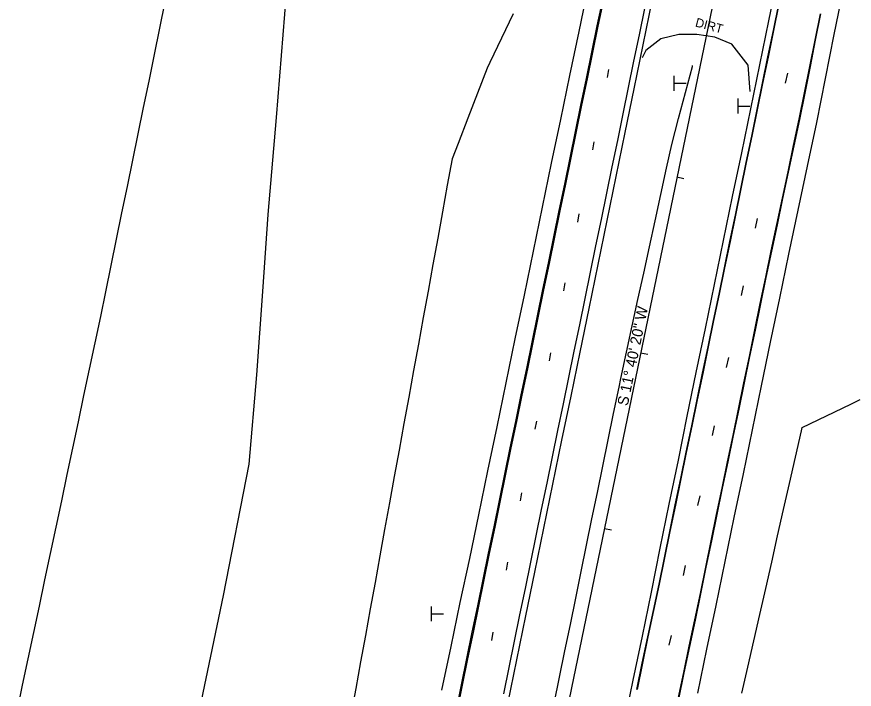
# Model space of a CAD drawing. Extents: x 2132221 to 2141942, y 535736 to 547298.
# Drawn here: x 2135703.9 to 2136170.8, y 536120.5 to 536495.3 of the extents above; entities that cross this region are included whole.
import ezdxf

# ---------------------------------------------------------------- set-up
doc = ezdxf.new("R2010")
doc.units = 0
for name, color, linetype in [('RD_EX_BldgApp', 7, 'Continuous'), ('RD_EX_Conc', 7, 'Continuous'), ('RD_EX_Driveway', 7, 'Continuous'), ('RD_EX_Driveway_txCode', 7, 'Continuous'), ('RD_EX_Fence_Other', 7, 'Continuous'), ('RD_EX_GuardRail', 7, 'Continuous'), ('RD_EX_Misc', 7, 'Continuous'), ('RD_EX_Road', 7, 'Continuous'), ('RD_EX_VEG', 7, 'Continuous'), ('RD_HC_Cl', 7, 'Continuous'), ('RD_HC_Data', 7, 'Continuous'), ('RD_HC_Data_Tic', 7, 'Continuous'), ('TOPO_E_TLIML-Line', 7, 'Continuous')]:
    doc.layers.add(name, color=color, linetype=linetype)

msp = doc.modelspace()

# ---------------------------------------------------------------- linework, layer by layer
at = {"layer": 'RD_EX_BldgApp'}
for p, q in [((2136070.24, 536462.33), (2136070.24, 536458.22)), ((2136070.24, 536458.22), (2136070.24, 536454.1)), ((2136070.24, 536458.22), (2136077.1, 536458.22)), ((2136105.85, 536449.67), (2136105.85, 536445.56)), ((2136105.85, 536445.56), (2136105.85, 536441.44)), ((2136105.85, 536445.56), (2136112.7, 536445.56)), ((2135934.97, 536166.67), (2135934.97, 536162.55)), ((2135934.97, 536162.55), (2135934.97, 536158.44)), ((2135934.97, 536162.55), (2135941.83, 536162.55))]:
    msp.add_line(p, q, dxfattribs=at)
at = {"layer": 'RD_EX_Conc'}
for points in [[(2135948.82, 536108.22), (2135951.86, 536122.91), (2135954.89, 536137.6), (2135957.9, 536152.29), (2135960.89, 536166.99), (2135963.94, 536181.68), (2135966.99, 536196.37), (2135970.01, 536211.06), (2135973.01, 536225.75), (2135976, 536240.45), (2135979.05, 536255.14), (2135982.1, 536269.83), (2135985.16, 536284.51), (2135988.2, 536299.2), (2135991.22, 536313.89), (2135994.25, 536328.58), (2135997.27, 536343.28), (2136000.3, 536357.97), (2136003.32, 536372.66), (2136006.35, 536387.35), (2136009.4, 536402.04), (2136012.43, 536416.73), (2136015.45, 536431.42), (2136018.46, 536446.11), (2136021.47, 536460.81), (2136024.49, 536475.5), (2136027.54, 536490.19), (2136030.62, 536504.87)], [(2136049.66, 536120.4), (2136052.66, 536135.1), (2136055.66, 536149.8), (2136058.9, 536164.45), (2136062.05, 536179.11), (2136065.03, 536193.81), (2136068.02, 536208.51), (2136071.02, 536223.21), (2136074.08, 536237.89), (2136077.14, 536252.58), (2136080.19, 536267.26), (2136083.25, 536281.95), (2136086.31, 536296.63), (2136089.35, 536311.32), (2136092.39, 536326.01), (2136095.42, 536340.7), (2136098.46, 536355.39), (2136101.49, 536370.08), (2136104.53, 536384.77), (2136107.56, 536399.46), (2136110.6, 536414.15), (2136113.63, 536428.84), (2136116.66, 536443.53), (2136119.69, 536458.22), (2136122.72, 536472.91), (2136125.75, 536487.6), (2136128.79, 536502.29)], [(2136073.01, 536115.07), (2136076.05, 536129.75), (2136079.09, 536144.44), (2136082.25, 536159.11), (2136085.36, 536173.78), (2136088.34, 536188.48), (2136091.33, 536203.18), (2136094.33, 536217.88), (2136097.43, 536232.55), (2136100.51, 536247.23), (2136103.55, 536261.92), (2136106.6, 536276.61), (2136109.66, 536291.29), (2136112.7, 536305.98), (2136115.73, 536320.67), (2136118.76, 536335.36), (2136121.8, 536350.05), (2136124.84, 536364.74), (2136127.94, 536379.42), (2136131.06, 536394.09), (2136134.21, 536408.75), (2136137.32, 536423.43), (2136140.4, 536438.11), (2136143.44, 536452.8), (2136146.42, 536467.5), (2136149.28, 536482.23), (2136152.25, 536496.93)]]:
    msp.add_lwpolyline(points, dxfattribs=at)
at = {"layer": 'RD_EX_Driveway'}
msp.add_lwpolyline([(2136112.71, 536453.63), (2136111.71, 536468.27), (2136102.62, 536479.95), (2136093.05, 536483.92), (2136083.12, 536485.46), (2136073.01, 536485.48), (2136063.01, 536482.98), (2136054.62, 536476.49), (2136052.53, 536472.45)], dxfattribs=at)
at = {"layer": 'RD_EX_Fence_Other'}
msp.add_lwpolyline([(2135895.12, 536767.27), (2135883.77, 536712.14), (2135871.61, 536651.94), (2135860.44, 536595.13), (2135857.57, 536552.99), (2135853.14, 536496.69), (2135848.56, 536439.08), (2135843.98, 536385.12), (2135840.93, 536342.24), (2135837.59, 536295.71), (2135833.23, 536245.95), (2135818.95, 536172.8), (2135802.2, 536092.65), (2135792.17, 536042.14), (2135779.97, 535986.39), (2135767.88, 535925.12), (2135755.58, 535870.87), (2135742.52, 535801.92)], dxfattribs=at)
at = {"layer": 'RD_EX_GuardRail'}
msp.add_lwpolyline([(2136003.49, 536112.6), (2136006.51, 536127.29), (2136009.52, 536141.99), (2136012.54, 536156.68), (2136015.55, 536171.38), (2136018.57, 536186.07), (2136021.58, 536200.76), (2136024.6, 536215.46), (2136027.61, 536230.15), (2136030.63, 536244.84), (2136033.65, 536259.54), (2136036.66, 536274.23), (2136039.68, 536288.93), (2136040.66, 536293.72), (2136043.85, 536308.37), (2136047.04, 536323.03), (2136050.23, 536337.69), (2136053.42, 536352.34), (2136056.61, 536367), (2136059.8, 536381.66), (2136062.99, 536396.31), (2136066.17, 536410.97), (2136069.03, 536424.11), (2136072.88, 536438.6), (2136076.72, 536453.1), (2136080.56, 536467.6), (2136080.7, 536468.12)], dxfattribs=at)
at = {"layer": 'RD_EX_Misc'}
for p, q in [((2136033.32, 536461.47), (2136034.08, 536465.96)), ((2136132.57, 536458.36), (2136133.74, 536463.87)), ((2136025.08, 536421.12), (2136025.85, 536425.61)), ((2136016.71, 536380.9), (2136017.48, 536385.39)), ((2136115.72, 536377.41), (2136116.89, 536382.91)), ((2136008.93, 536342.6), (2136009.7, 536347.09)), ((2136107.95, 536339.87), (2136109.12, 536345.37)), ((2136000.84, 536303.55), (2136001.61, 536308.04)), ((2136099.65, 536299.92), (2136100.82, 536305.42)), ((2135993.02, 536265.46), (2135993.78, 536269.95)), ((2136091.81, 536261.89), (2136092.98, 536267.39)), ((2135984.74, 536225.46), (2135985.51, 536229.95)), ((2136083.7, 536222.88), (2136084.87, 536228.38)), ((2135976.91, 536186.84), (2135977.68, 536191.32)), ((2136075.64, 536183.92), (2136076.81, 536189.42)), ((2135968.71, 536147.78), (2135969.48, 536152.27)), ((2136067.71, 536145.01), (2136068.88, 536150.51))]:
    msp.add_line(p, q, dxfattribs=at)
for points in [[(2135949.4, 536108.1), (2135952.43, 536122.79), (2135955.46, 536137.48), (2135958.47, 536152.18), (2135961.46, 536166.87), (2135964.51, 536181.56), (2135967.56, 536196.25), (2135970.59, 536210.94), (2135973.58, 536225.64), (2135976.57, 536240.34), (2135979.62, 536255.02), (2135982.67, 536269.71), (2135985.73, 536284.39), (2135988.77, 536299.08), (2135991.8, 536313.77), (2135994.82, 536328.47), (2135997.84, 536343.16), (2136000.87, 536357.85), (2136003.89, 536372.54), (2136006.92, 536387.23), (2136009.97, 536401.92), (2136013.01, 536416.61), (2136016.02, 536431.3), (2136019.03, 536446), (2136022.04, 536460.69), (2136025.07, 536475.38), (2136028.11, 536490.07), (2136031.2, 536504.75)], [(2136049.91, 536120.35), (2136052.91, 536135.05), (2136055.91, 536149.75), (2136059.14, 536164.39), (2136062.29, 536179.06), (2136065.27, 536193.76), (2136068.27, 536208.46), (2136071.26, 536223.16), (2136074.32, 536237.84), (2136077.38, 536252.53), (2136080.44, 536267.21), (2136083.49, 536281.9), (2136086.55, 536296.58), (2136089.59, 536311.27), (2136092.63, 536325.96), (2136095.66, 536340.65), (2136098.7, 536355.34), (2136101.74, 536370.03), (2136104.77, 536384.72), (2136107.81, 536399.41), (2136110.84, 536414.1), (2136113.87, 536428.79), (2136116.9, 536443.48), (2136119.93, 536458.17), (2136122.97, 536472.86), (2136126, 536487.55), (2136129.03, 536502.24)], [(2135975.37, 536117.9), (2135978.37, 536132.6), (2135981.39, 536147.29), (2135984.42, 536161.98), (2135987.45, 536176.67), (2135990.47, 536191.36), (2135993.5, 536206.05), (2135996.52, 536220.74), (2135999.55, 536235.44), (2136002.6, 536250.12), (2136005.64, 536264.81), (2136008.68, 536279.5), (2136011.7, 536294.19), (2136014.73, 536308.88), (2136017.75, 536323.58), (2136020.78, 536338.27), (2136023.8, 536352.96), (2136026.83, 536367.65), (2136029.85, 536382.34), (2136032.88, 536397.04), (2136035.9, 536411.73), (2136038.93, 536426.42), (2136041.96, 536441.11), (2136044.98, 536455.8), (2136048.01, 536470.49), (2136051.03, 536485.18), (2136054.06, 536499.88)], [(2136072.7, 536115.13), (2136075.74, 536129.82), (2136078.78, 536144.51), (2136081.94, 536159.17), (2136085.04, 536173.85), (2136088.03, 536188.55), (2136091.02, 536203.25), (2136094.02, 536217.94), (2136097.12, 536232.62), (2136100.2, 536247.3), (2136103.24, 536261.99), (2136106.29, 536276.67), (2136109.35, 536291.36), (2136112.38, 536306.05), (2136115.41, 536320.74), (2136118.45, 536335.43), (2136121.49, 536350.12), (2136124.52, 536364.81), (2136127.63, 536379.48), (2136130.75, 536394.16), (2136133.9, 536408.82), (2136137.01, 536423.49), (2136140.09, 536438.17), (2136143.13, 536452.86), (2136146.1, 536467.56), (2136148.96, 536482.29), (2136151.94, 536496.99)]]:
    msp.add_lwpolyline(points, dxfattribs=at)
at = {"layer": 'RD_EX_Road'}
for points in [[(2136042.64, 536101.12), (2136047.65, 536125.62), (2136052.74, 536150.09), (2136057.72, 536174.59), (2136062.7, 536199.09), (2136067.7, 536223.61), (2136072.81, 536248.14), (2136077.68, 536272.66), (2136082.78, 536297.13), (2136087.87, 536321.61), (2136092.88, 536346.09), (2136097.95, 536370.56), (2136103.02, 536395.04), (2136108.11, 536419.51), (2136113.18, 536443.99), (2136118.23, 536468.48), (2136123.19, 536492.98), (2136128.25, 536517.46)], [(2135940.92, 536120), (2135946.14, 536144.41), (2135951.17, 536168.9), (2135956.43, 536193.34), (2135961.56, 536217.81), (2135966.58, 536242.3), (2135971.7, 536266.77), (2135976.8, 536291.24), (2135981.85, 536315.73), (2135986.9, 536340.21), (2135991.97, 536364.69), (2135997.02, 536389.18), (2136002.11, 536413.65), (2136007.19, 536438.13), (2136012.24, 536462.62), (2136017.38, 536487.08), (2136022.52, 536511.55)], [(2136083.61, 536118.31), (2136088.64, 536142.8), (2136093.91, 536167.24), (2136098.9, 536191.74), (2136103.89, 536216.2), (2136109.04, 536240.59), (2136114.08, 536265.07), (2136119.18, 536289.55), (2136124.21, 536314.04), (2136129.27, 536338.54), (2136134.36, 536363.03), (2136139.49, 536387.5), (2136144.72, 536411.95), (2136149.89, 536436.41), (2136154.86, 536460.91), (2136159.63, 536485.45), (2136164.69, 536509.93)], [(2135977.72, 536112.36), (2135982.63, 536136.9), (2135987.69, 536161.38), (2135992.75, 536185.86), (2135997.75, 536210.35), (2136002.8, 536234.84), (2136007.85, 536259.32), (2136012.91, 536283.81), (2136017.95, 536308.29), (2136022.96, 536332.79), (2136028, 536357.27), (2136033.03, 536381.76), (2136038.07, 536406.25), (2136043.12, 536430.73), (2136048.14, 536455.22), (2136053.18, 536479.71), (2136058.23, 536504.2)]]:
    msp.add_lwpolyline(points, dxfattribs=at)
at = {"layer": 'RD_EX_VEG'}
for points in [[(2135980.61, 536496.85), (2135974.13, 536483.33), (2135967.64, 536469.8), (2135966.15, 536466.69), (2135960.74, 536452.69), (2135955.34, 536438.7), (2135949.94, 536424.71), (2135946.65, 536416.18), (2135943.96, 536401.42), (2135941.27, 536386.67), (2135938.59, 536371.91), (2135935.9, 536357.15), (2135933.21, 536342.4), (2135930.52, 536327.64), (2135927.83, 536312.88), (2135925.14, 536298.12), (2135922.46, 536283.37), (2135919.77, 536268.61), (2135917.08, 536253.85), (2135914.39, 536239.1), (2135911.7, 536224.34), (2135909.02, 536209.58), (2135906.33, 536194.82), (2135903.64, 536180.07), (2135900.95, 536165.31), (2135898.26, 536150.55), (2135895.58, 536135.8), (2135892.89, 536121.04), (2135890.2, 536106.28)], [(2136108.12, 536118.26), (2136111.45, 536132.89), (2136114.78, 536147.51), (2136118.12, 536162.14), (2136121.45, 536176.76), (2136124.78, 536191.39), (2136128.11, 536206.01), (2136131.45, 536220.64), (2136134.78, 536235.26), (2136138.11, 536249.89), (2136141.44, 536264.51), (2136141.87, 536266.36), (2136155.36, 536272.92), (2136168.85, 536279.48), (2136174.04, 536282)]]:
    msp.add_lwpolyline(points, dxfattribs=at)
at = {"layer": 'RD_HC_Cl'}
msp.add_line((2136156.9, 536817.18), (2135945, 535791.47), dxfattribs=at)
at = {"layer": 'RD_HC_Data_Tic'}
for p, q in [((2136071.96, 536406.02), (2136075.88, 536405.21)), ((2136051.73, 536308.09), (2136055.65, 536307.28)), ((2136031.5, 536210.16), (2136035.41, 536209.35))]:
    msp.add_line(p, q, dxfattribs=at)
at = {"layer": 'TOPO_E_TLIML-Line'}
msp.add_lwpolyline([(2135786.55, 536503.56), (2135783.53, 536488.87), (2135780.51, 536474.17), (2135777.49, 536459.48), (2135774.47, 536444.79), (2135771.45, 536430.09), (2135768.43, 536415.4), (2135765.41, 536400.71), (2135762.39, 536386.01), (2135759.37, 536371.32), (2135756.36, 536356.63), (2135753.34, 536341.94), (2135750.51, 536328.21), (2135747.41, 536313.53), (2135744.3, 536298.86), (2135741.19, 536284.19), (2135738.09, 536269.51), (2135734.98, 536254.84), (2135731.87, 536240.16), (2135728.77, 536225.49), (2135725.66, 536210.81), (2135722.55, 536196.14), (2135719.45, 536181.46), (2135716.34, 536166.79), (2135713.23, 536152.11), (2135710.13, 536137.44), (2135707.02, 536122.76), (2135703.91, 536108.09)], dxfattribs=at)

# ---------------------------------------------------------------- texts
at = {"layer": 'RD_EX_Driveway_txCode'}
msp.add_text('DIRT', height=5, rotation=345.0642, dxfattribs=at).set_placement((2136081.81, 536489.95))
at = {"layer": 'RD_HC_Data'}
msp.add_text('S 11%%d 40\' 20" W', height=6, rotation=78.3278, dxfattribs=at).set_placement((2136044.52, 536278.13))

doc.saveas('drawing.dxf')
